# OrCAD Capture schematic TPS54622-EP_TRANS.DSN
size D; title: TPS54622-EP, 4.5V to 17V Input, 6A Synchronous Step Down; rev: 1.0; note: Datasheet: SLVSFN6   EVM: SLVU441A
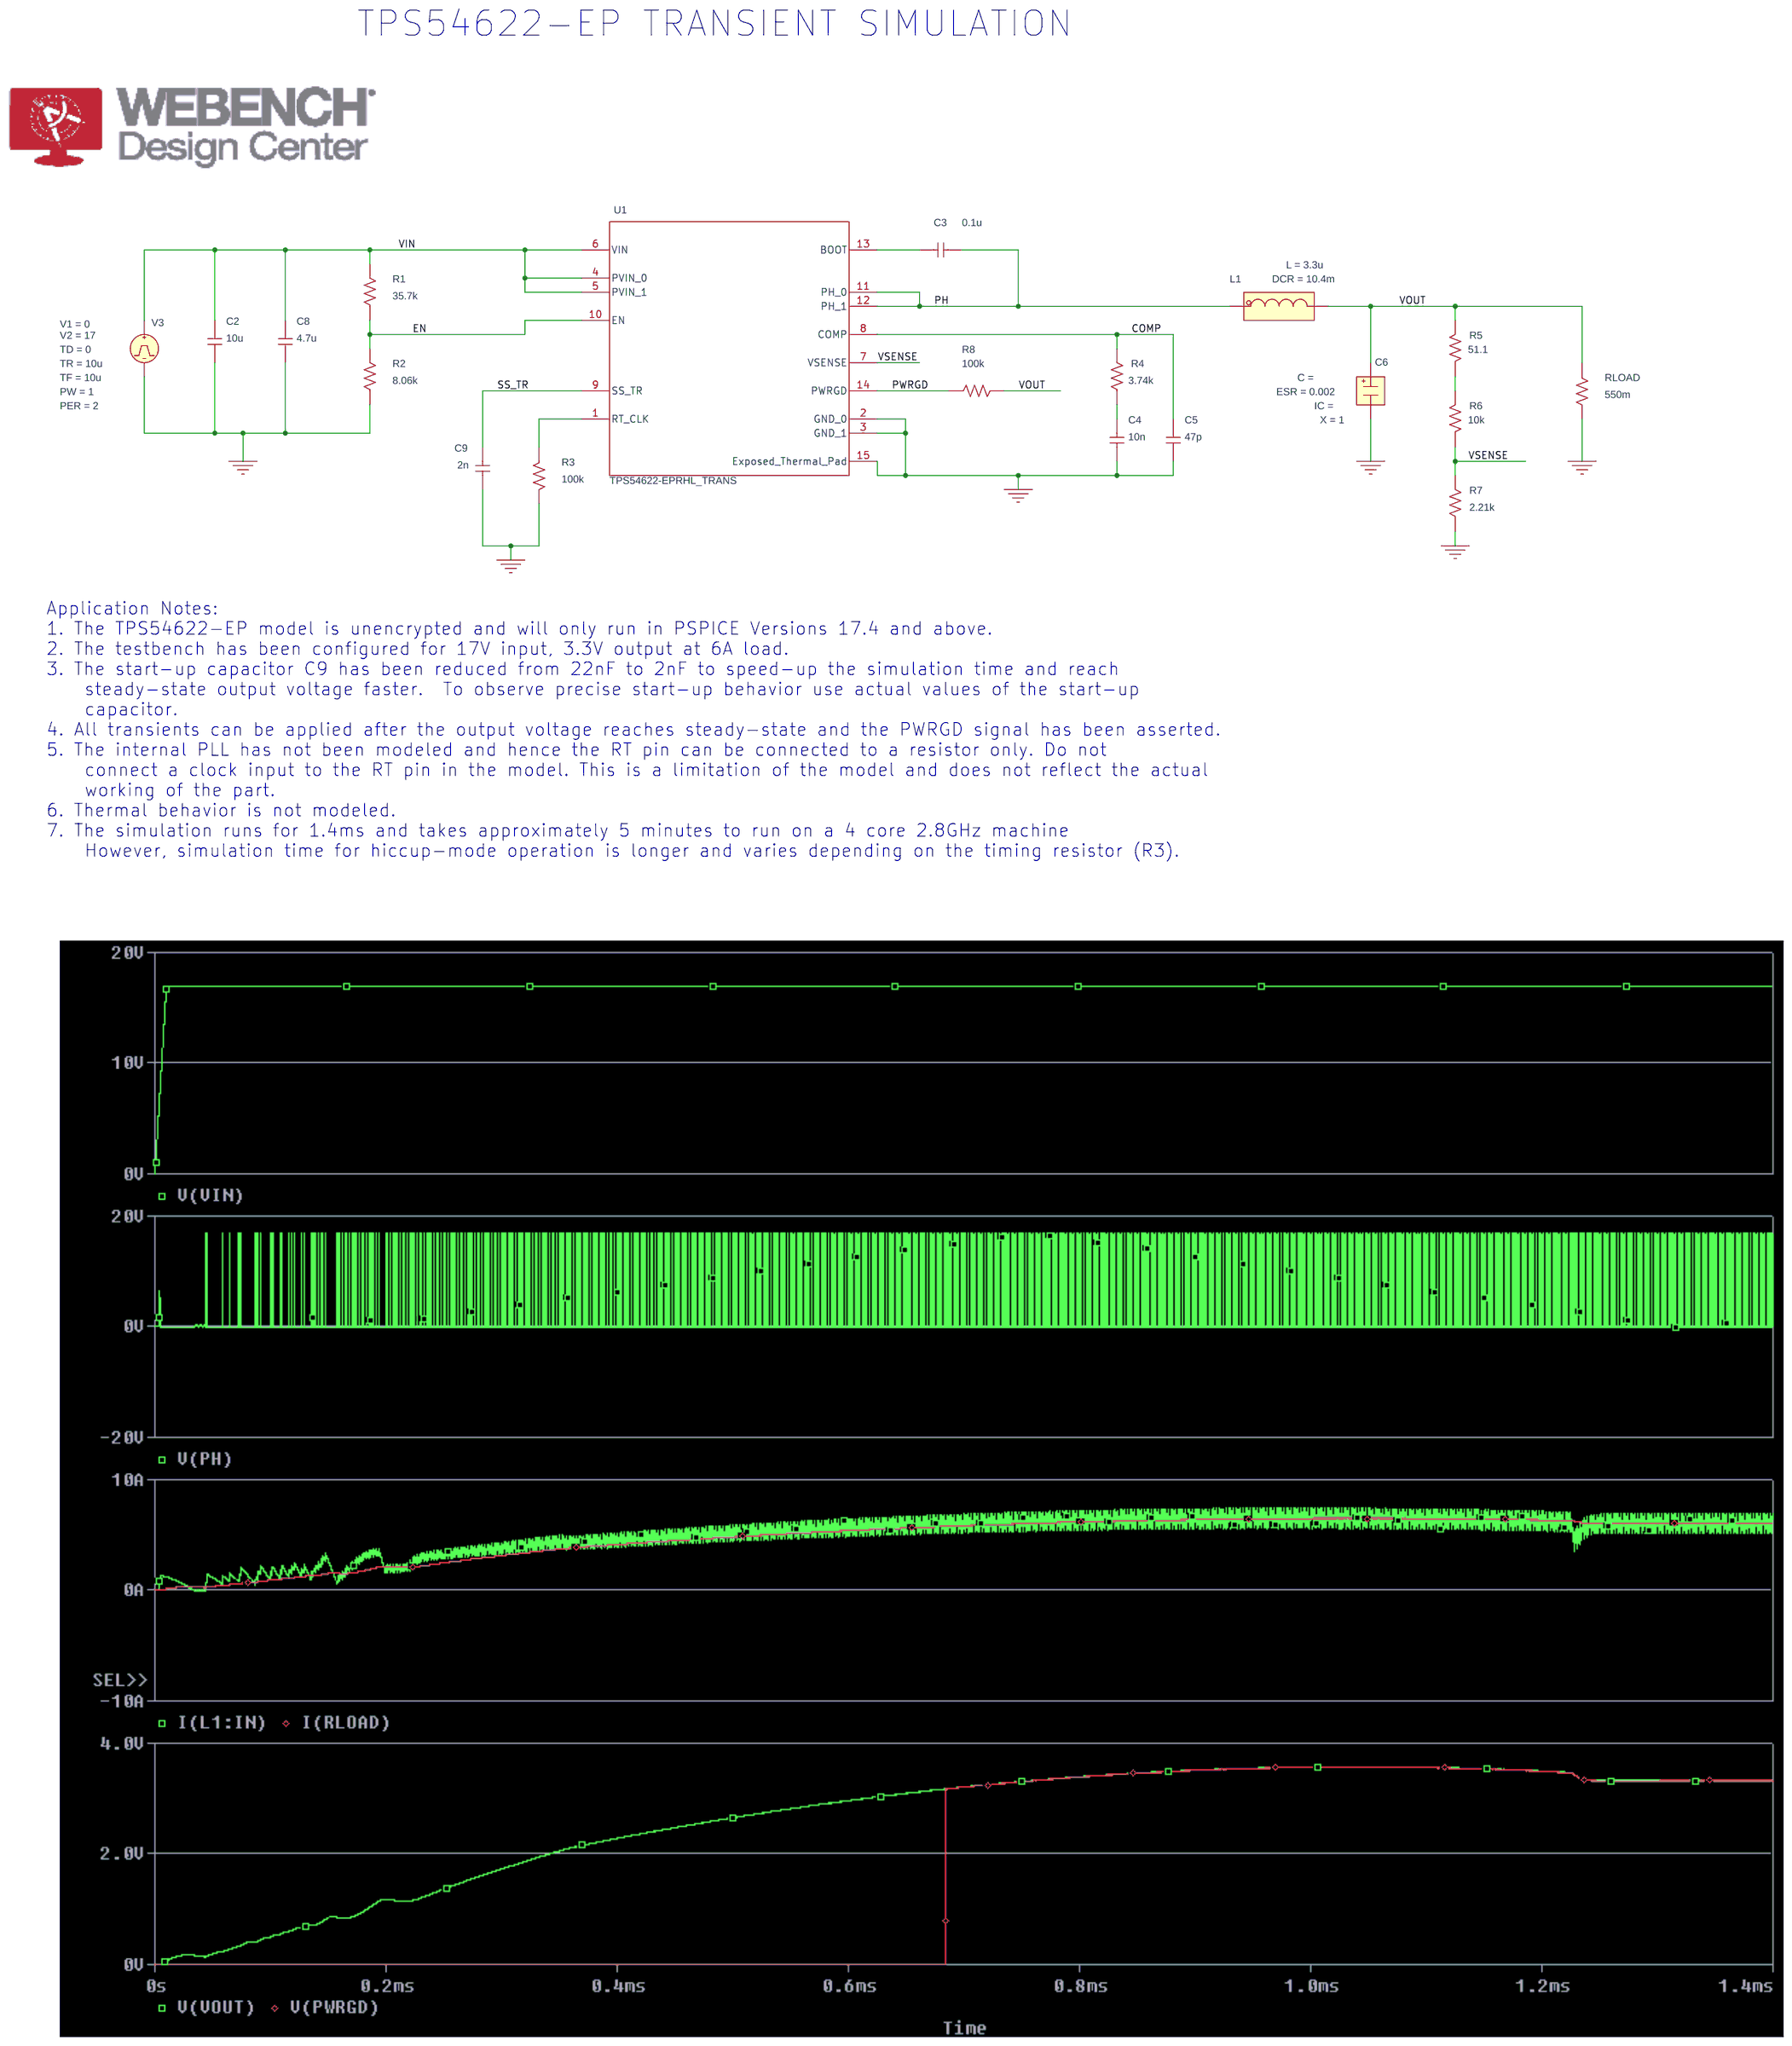
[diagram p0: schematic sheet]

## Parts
C2  10u  [RAD/CK05]
C3  0.1u  [RAD/CK05]
C4  10n  [RAD/CK05]
C5  47p  [RAD/CK05]
C6  CESR
C8  4.7u  [RAD/CK05]
C9  2n  [RAD/CK05]
L1  LDCR
R1  35.7k  [AX/RC05]
R2  8.06k  [AX/RC05]
R3  100k  [AX/RC05]
R4  3.74k  [AX/RC05]
R5  51.1  [AX/RC05]
R6  10k  [AX/RC05]
R7  2.21k  [AX/RC05]
R8  100k  [AX/RC05]
RLOAD  550m  [AX/RC05]
U1  TPS54622-EPRHL_TRANS  [RHL0014A-MFG]
V3  VPULSE

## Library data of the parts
C2-C5 C8 C9 = C
C6 = CESR: ESR: 0.002; X: 1
L1 = LDCR: DCR: 10.4m; IC: 0; L: 3.3u; PSpiceTemplate: X^@REFDES %IN %OUT @MODEL PARAMS:  ?L|L=@L||L=1u|  ?DCR|DCR=@DCR||DCR=0.01| ?IC|IC=@IC||IC=0|
R1-R8 RLOAD = R
U1 = TPS54622-EPRHL_TRANS
V3 = VPULSE: PER: 2; PW: 1; TD: 0; TF: 10u; TR: 10u; V1: 0; V2: 17

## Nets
VIN: C2.2 C8.2 R1.2 U1.4(PVIN_0) U1.5(PVIN_1) U1.6(VIN) V3.1(+)
0: C2.1 C4.1 C5.1 C6.3(OUT) C8.1 C9.1 R2.1 R3.2 R7.1 RLOAD.2 U1.2(GND_0) U1.3(GND_1) U1.15(Exposed_Thermal_Pad) V3.2(-)
COMP: C5.2 R4.2 U1.8(COMP)
EN: R1.1 R2.2 U1.10(EN)
PH: C3.1 L1.1(IN) U1.11(PH_0) U1.12(PH_1)
PWRGD: R8.1 U1.14(PWRGD)
SS_TR: C9.2 U1.9(SS_TR)
VOUT: C6.1(IN) L1.3(OUT) R5.2 R8.2 RLOAD.1
VSENSE: R6.1 R7.2 U1.7(VSENSE)
N16661693: R3.1 U1.1(RT_CLK)
N16661897: C4.2 R4.1
N16662485: R5.1 R6.2
N16662705: C3.2 U1.13(BOOT)

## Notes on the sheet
- TPS54622-EP TRANSIENT SIMULATION
- Application Notes:
  1. The TPS54622-EP model is unencrypted and will only run in PSPICE Versions 17.4 and above.
  2. The testbench has been configured for 17V input, 3.3V output at 6A load.
  3. The start-up capacitor C9 has been reduced from 22nF to 2nF to speed-up the simulation time and reach
      steady-state output voltage faster.  To observe precise start-up behavior use actual values of the start-up
      capacitor.
  4. All transients can be applied after the output voltage reaches steady-state and the PWRGD signal has been asserted.
  5. The internal PLL has not been modeled and hence the RT pin can be connected to a resistor only. Do not
      connect a clock input to the RT pin in the model. This is a limitation of the model and does not reflect the actual
      working of the part.
  6. Thermal behavior is not modeled.
  7. The simulation runs for 1.4ms and takes approximately 5 minutes to run on a 4 core 2.8GHz machine
      However, simulation time for hiccup-mode operation is longer and varies depending on the timing resistor (R3).
